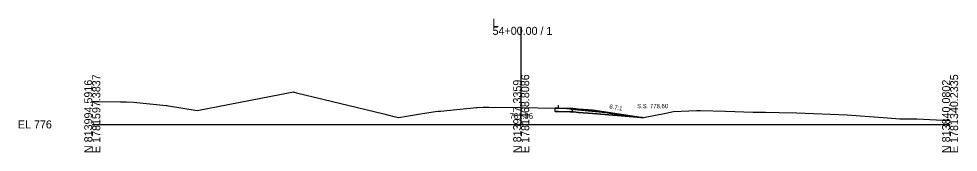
# Model space of a CAD drawing. Extents: x -26 to 7903, y -10 to 9573.
# Drawn here: x 1974.3 to 2302.8, y 4990.3 to 5036.9 of the extents above; entities that cross this region are included whole.
import ezdxf

# ---------------------------------------------------------------- set-up
doc = ezdxf.new("R2010")
doc.units = 0
for name, color, linetype in [('Exist Cross Section Cell', 7, 'Continuous'), ('Exist XS Center Line Elevation Label', 7, 'Continuous'), ('Exist XS Ground Line', 7, 'Continuous'), ('Prop XS Ditch Slope Text', 7, 'Continuous'), ('Prop XS Dump Level', 7, 'Continuous'), ('Prop XS Earthwork Shape', 7, 'Continuous'), ('Prop XS EOT Tick Mark', 7, 'Continuous'), ('Prop XS Finish Grade', 7, 'Continuous'), ('Prop XS Finish Grade Earthwork', 7, 'Continuous'), ('Prop XS Finish Grade Paved Shoulder', 7, 'Continuous'), ('Prop XS Finish Grade Pavement', 7, 'Continuous'), ('Prop XS Hydro Typical Ditch Data', 7, 'Continuous'), ('Prop XS Pvmt Edge Slope', 7, 'Continuous'), ('Prop XS SS Elevation Text', 7, 'Continuous'), ('Prop XS Subgrade Earthwork', 7, 'Continuous'), ('Scratch_Level_3', 7, 'Continuous'), ('Scratch_Level_6', 7, 'Continuous')]:
    doc.layers.add(name, color=color, linetype=linetype)

msp = doc.modelspace()

# ---------------------------------------------------------------- linework, layer by layer
at = {"layer": 'Exist Cross Section Cell'}
for p, q in [((2150, 5000), (2150, 5034.06)), ((2000, 5000), (2150, 5000)), ((2150, 5000), (2300, 5000))]:
    msp.add_line(p, q, dxfattribs=at)
at = {"layer": 'Exist XS Ground Line'}
for p, q in [((2036.69, 5004.89), (2069.85, 5011.28)), ((2069.85, 5011.28), (2070.21, 5011.35)), ((2070.21, 5011.35), (2070.57, 5011.27)), ((2070.57, 5011.27), (2071.42, 5011.06)), ((2071.42, 5011.06), (2102.02, 5003.67)), ((2000, 5007.99), (2002.32, 5008.02)), ((2002.32, 5008.02), (2009.88, 5007.92)), ((2009.88, 5007.92), (2011.45, 5007.9)), ((2011.45, 5007.9), (2011.96, 5007.88)), ((2011.96, 5007.88), (2014.46, 5007.76)), ((2014.46, 5007.76), (2025.79, 5006.6)), ((2025.79, 5006.6), (2026.24, 5006.56)), ((2026.24, 5006.56), (2026.65, 5006.49)), ((2026.65, 5006.49), (2036.69, 5004.89)), ((2102.02, 5003.67), (2105.5, 5002.81)), ((2109.86, 5002.9), (2114.83, 5003.64)), ((2114.83, 5003.64), (2119.23, 5004.4)), ((2119.23, 5004.4), (2120.82, 5004.59)), ((2120.82, 5004.59), (2121.73, 5004.65)), ((2121.73, 5004.65), (2127.33, 5005.18)), ((2127.33, 5005.18), (2132.13, 5005.65)), ((2132.13, 5005.65), (2134.24, 5005.86)), ((2134.24, 5005.86), (2134.68, 5005.9)), ((2134.68, 5005.9), (2136.68, 5005.99)), ((2136.68, 5005.99), (2138.35, 5006.07)), ((2138.35, 5006.07), (2138.72, 5006.07)), ((2138.72, 5006.07), (2150.01, 5005.96)), ((2150.01, 5005.96), (2161.91, 5005.72)), ((2161.91, 5005.72), (2162.68, 5005.69)), ((2162.68, 5005.69), (2165.92, 5005.53)), ((2165.92, 5005.53), (2168.11, 5005.32)), ((2168.11, 5005.32), (2168.81, 5005.25)), ((2168.81, 5005.25), (2179.5, 5004.19)), ((2179.5, 5004.19), (2180.83, 5003.97)), ((2180.83, 5003.97), (2184.17, 5003.51)), ((2192.75, 5002.45), (2200.64, 5003.98)), ((2200.64, 5003.98), (2203.25, 5004.51)), ((2203.25, 5004.51), (2211.37, 5004.88)), ((2211.37, 5004.88), (2212.07, 5004.91)), ((2212.07, 5004.91), (2212.7, 5004.88)), ((2212.7, 5004.88), (2221.48, 5004.64)), ((2221.48, 5004.64), (2231.18, 5004.29)), ((2231.18, 5004.29), (2235.39, 5004.25)), ((2235.39, 5004.25), (2240.21, 5004.19)), ((2240.21, 5004.19), (2246.39, 5004.03)), ((2246.39, 5004.03), (2264.06, 5003.33)), ((2105.5, 5002.81), (2107.18, 5002.41)), ((2107.18, 5002.41), (2109.86, 5002.9)), ((2184.17, 5003.51), (2184.63, 5003.44)), ((2184.63, 5003.44), (2186.38, 5003.16)), ((2186.38, 5003.16), (2192.44, 5002.39)), ((2192.44, 5002.39), (2192.75, 5002.45)), ((2264.06, 5003.33), (2278.1, 5002.3)), ((2278.1, 5002.3), (2282.43, 5002)), ((2282.43, 5002), (2288.32, 5001.89)), ((2288.32, 5001.89), (2295.23, 5001.59)), ((2295.23, 5001.59), (2297.21, 5001.53)), ((2297.21, 5001.53), (2300, 5001.47))]:
    msp.add_line(p, q, dxfattribs=at)
at = {"layer": 'Prop XS Dump Level'}
msp.add_line((2163.08, 5005.7), (2161.92, 5005.72), dxfattribs=at)
msp.add_line((2163.08, 5005.7), (2161.92, 5005.72), dxfattribs=at)
at = {"layer": 'Prop XS Earthwork Shape'}
for points in [[(2186.38, 5003.16), (2191.81, 5002.47), (2175.08, 5003.81), (2170.08, 5004.21), (2168.35, 5004.35), (2167.08, 5004.37), (2163.08, 5004.45), (2161.91, 5004.47), (2161.91, 5005.72), (2162.68, 5005.69), (2165.92, 5005.53), (2168.11, 5005.32), (2168.81, 5005.25), (2179.5, 5004.19), (2180.83, 5003.97), (2184.17, 5003.51), (2184.63, 5003.44)], [(2191.81, 5002.47), (2192.44, 5002.39), (2192, 5002.45)]]:
    msp.add_lwpolyline(points, close=True, dxfattribs=at)
at = {"layer": 'Prop XS EOT Tick Mark'}
msp.add_line((2163.08, 5005.7), (2163.08, 5006.7), dxfattribs=at)
at = {"layer": 'Prop XS Finish Grade'}
for p, q in [((2167.08, 5005.62), (2170.08, 5005.38)), ((2170.08, 5005.38), (2175.08, 5004.98)), ((2175.08, 5004.98), (2192, 5002.45))]:
    msp.add_line(p, q, dxfattribs=at)
at = {"layer": 'Prop XS Finish Grade Earthwork'}
msp.add_line((2192, 5002.45), (2192.44, 5002.39), dxfattribs=at)
at = {"layer": 'Prop XS Finish Grade Paved Shoulder'}
msp.add_line((2163.08, 5005.7), (2167.08, 5005.62), dxfattribs=at)
at = {"layer": 'Prop XS Finish Grade Pavement'}
msp.add_line((2161.91, 5005.72), (2163.08, 5005.7), dxfattribs=at)
at = {"layer": 'Prop XS Hydro Typical Ditch Data'}
msp.add_line((2175.08, 5004.98), (2192.44, 5002.39), dxfattribs=at)
at = {"layer": 'Prop XS Pvmt Edge Slope'}
msp.add_line((2167.08, 5005.62), (2168.35, 5004.35), dxfattribs=at)
at = {"layer": 'Prop XS Subgrade Earthwork'}
for p, q in [((2161.91, 5004.47), (2161.91, 5005.72)), ((2161.91, 5004.47), (2163.08, 5004.45)), ((2163.08, 5004.45), (2167.08, 5004.37)), ((2167.08, 5004.37), (2168.35, 5004.35)), ((2168.35, 5004.35), (2170.08, 5004.21)), ((2170.08, 5004.21), (2175.08, 5003.81)), ((2175.08, 5003.81), (2192, 5002.45))]:
    msp.add_line(p, q, dxfattribs=at)
at = {"layer": 'Scratch_Level_3'}
for p, q in [((2170.08, 5005.38), (2167.08, 5005.62)), ((2167.08, 5005.62), (2168.35, 5004.35)), ((2168.35, 5004.35), (2170.08, 5004.21)), ((2175.08, 5004.98), (2170.08, 5005.38)), ((2170.08, 5004.21), (2175.08, 5003.81)), ((2192, 5002.45), (2175.08, 5004.98)), ((2175.08, 5003.81), (2192, 5002.45))]:
    msp.add_line(p, q, dxfattribs=at)
at = {"layer": 'Scratch_Level_6'}
msp.add_lwpolyline([(2186.38, 5003.16), (2191.81, 5002.47), (2175.08, 5003.81), (2170.08, 5004.21), (2168.35, 5004.35), (2167.08, 5004.37), (2163.08, 5004.45), (2161.91, 5004.47), (2161.91, 5005.72), (2162.68, 5005.69), (2165.92, 5005.53), (2168.11, 5005.32), (2168.81, 5005.25), (2179.5, 5004.19), (2180.83, 5003.97), (2184.17, 5003.51), (2184.63, 5003.44)], close=True, dxfattribs=at)

# ---------------------------------------------------------------- texts
at = {"layer": 'Exist Cross Section Cell'}
for s, p in [('L', (2140, 5034.06)), ('54+00.00 / 1', (2140, 5031.26)), ('EL 776', (1974, 4998.6))]:
    msp.add_text(s, height=2.8, dxfattribs=at).set_placement(p)
for s, p in [('E 1781597.3837', (2002.8, 4990)), ('E 1781468.8086', (2152.8, 4990)), ('E 1781340.2335', (2302.8, 4990)), ('N 813994.5916', (2000, 4990)), ('N 813917.3359', (2150, 4990)), ('N 813840.0802', (2300, 4990))]:
    msp.add_text(s, height=2.8, rotation=90, dxfattribs=at).set_placement(p)
at = {"layer": 'Exist XS Center Line Elevation Label'}
msp.add_text('781.96', height=2, dxfattribs=at).set_placement((2145.97, 5001.96))
at = {"layer": 'Prop XS Ditch Slope Text'}
msp.add_text('6.7:1', height=1.5, rotation=350.5377, dxfattribs=at).set_placement((2180.75, 5005.56))
at = {"layer": 'Prop XS Dump Level'}
for s, height, p in [('Eop', 0.3, (2161.91, 5005.42)), ('Case4', 0.04, (2175.08, 5004.94))]:
    msp.add_text(s, height=height, dxfattribs=at).set_placement(p)
at = {"layer": 'Prop XS SS Elevation Text'}
msp.add_text('S.S. 778.60', height=1.5, dxfattribs=at).set_placement((2190.55, 5005.65))

doc.saveas('drawing.dxf')
